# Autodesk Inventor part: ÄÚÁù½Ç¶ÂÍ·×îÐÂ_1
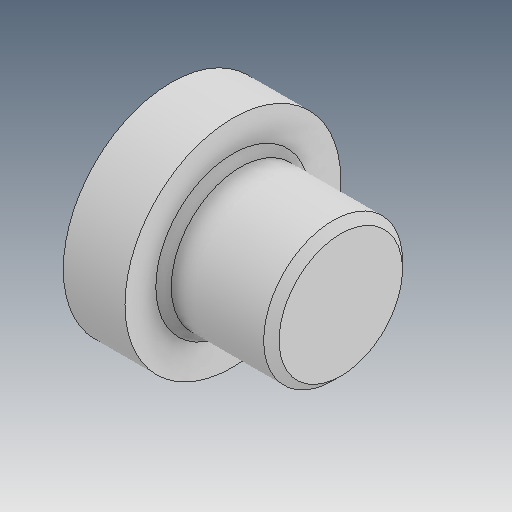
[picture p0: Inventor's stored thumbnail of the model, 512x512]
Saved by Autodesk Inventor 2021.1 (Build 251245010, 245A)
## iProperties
Created: 2019-04
Part Number: ÄÚÁù½Ç¶ÂÍ·×îÐÂ_1
Material: Ogólny
Document SubType Name: Modeling
Designer: user
Density: 1 g/cm^3
Appearance: Domyślna
Author: user
Revision Number: ÈÎºÎ
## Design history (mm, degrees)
feature "ÊäÈë1"
node "Bryła1"
